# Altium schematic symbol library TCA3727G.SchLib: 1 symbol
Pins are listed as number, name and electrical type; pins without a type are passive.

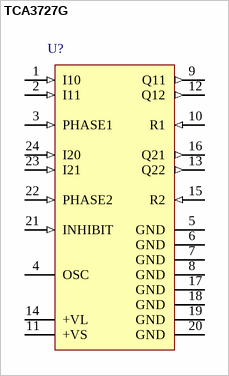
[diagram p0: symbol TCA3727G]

## TCA3727G
designator U?
2-Phase Stepper Motor Driver Bipolar IC, -40 to 125 degC, PG-DSO-24-13, Reel, Green; Manufacturer: Infineon; PartNumber: TCA3727G; Green: TRUE; IPeak: 2 x 1 A; Iq: 2 x 0.75 A; Iq (typ): 20 uA; Protect: Overtemp. e.a.
footprint INF-PG-DSO-24-13_N (SOP, 24-Leads, Body 15.4x7.5mm, Pitch 1.27mm, IPC Medium Density)
footprint INF-PG-DSO-24-13_L (SOP, 24-Leads, Body 15.4x7.5mm, Pitch 1.27mm, IPC High Density)
footprint INF-PG-DSO-24-13_M (SOP, 24-Leads, Body 15.4x7.5mm, Pitch 1.27mm, IPC Low Density)
pins: 1 I10 (in) "Digital control inputs IX0, IX1 for the magnitude of the current of the particular phase. See Table 2.", 2 I11 (in) "Digital control inputs IX0, IX1 for the magnitude of the current of the particular phase. See Table 2.", 3 PHASE1 (in) "Input Phase 1; controls the current through phase winding 1. On H-potential the phase current flows from Q11 to Q12, on L-potential in the reverse direction", 4 OSC "Oscillator; works at approx. 25 kHz if this pin is wired to ground across 2.2 nF.", 5 GND (power) "Ground; all pins are connected internally.", 6 GND (power) "Ground; all pins are connected internally.", 7 GND (power) "Ground; all pins are connected internally.", 8 GND (power) "Ground; all pins are connected internally.", 9 Q11 (out) "Push-pull outputs Q11, Q12 for phase 1 with integrated free-wheeling diodes.", 10 R1 (in) "Resistor R1 for sensing the current in phase 1.", 11 +VS (power) "Supply voltage; block to ground, as close as possible to the IC, with a stable electrolytic capacitor of at least 10 uF in parallel with a ceramic capacitor of 220 nF.", 12 Q12 (out) "Push-pull outputs Q11, Q12 for phase 1 with integrated free-wheeling diodes.", 13 Q22 (out) "Push-pull outputs Q22, Q21 for phase 2 with integrated free wheeling diodes.", 14 +VL (power) "Logic supply voltage; either supply with 5 V or connect to +VS across a series resistor. A Z-diode of approx. 7 V is integrated. In both cases block to ground directly on the IC with a stable electrolytic capacitor of 10 uF (See Datasheet)", 15 R2 (in) "Resistor R2 for sensing the current in phase 2.", 16 Q21 (out) "Push-pull outputs Q22, Q21 for phase 2 with integrated free wheeling diodes.", 17 GND (power) "Ground; all pins are connected internally.", 18 GND (power) "Ground; all pins are connected internally.", 19 GND (power) "Ground; all pins are connected internally.", 20 GND (power) "Ground; all pins are connected internally.", 21 INHIBIT (in) "Inhibit input; the IC can be put on standby by low potential on this pin. This reduces the current consumption substantially", 22 PHASE2 (in) "Input phase 2; controls the current flow through phase winding 2. On H-potential the phase current flows from Q21 to Q22, on L potential in the reverse direction", 23 I21 (in) "Digital control inputs IX0, IX1 for the magnitude of the current of the particular phase. See Table 2.", 24 I20 (in) "Digital control inputs IX0, IX1 for the magnitude of the current of the particular phase. See Table 2."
